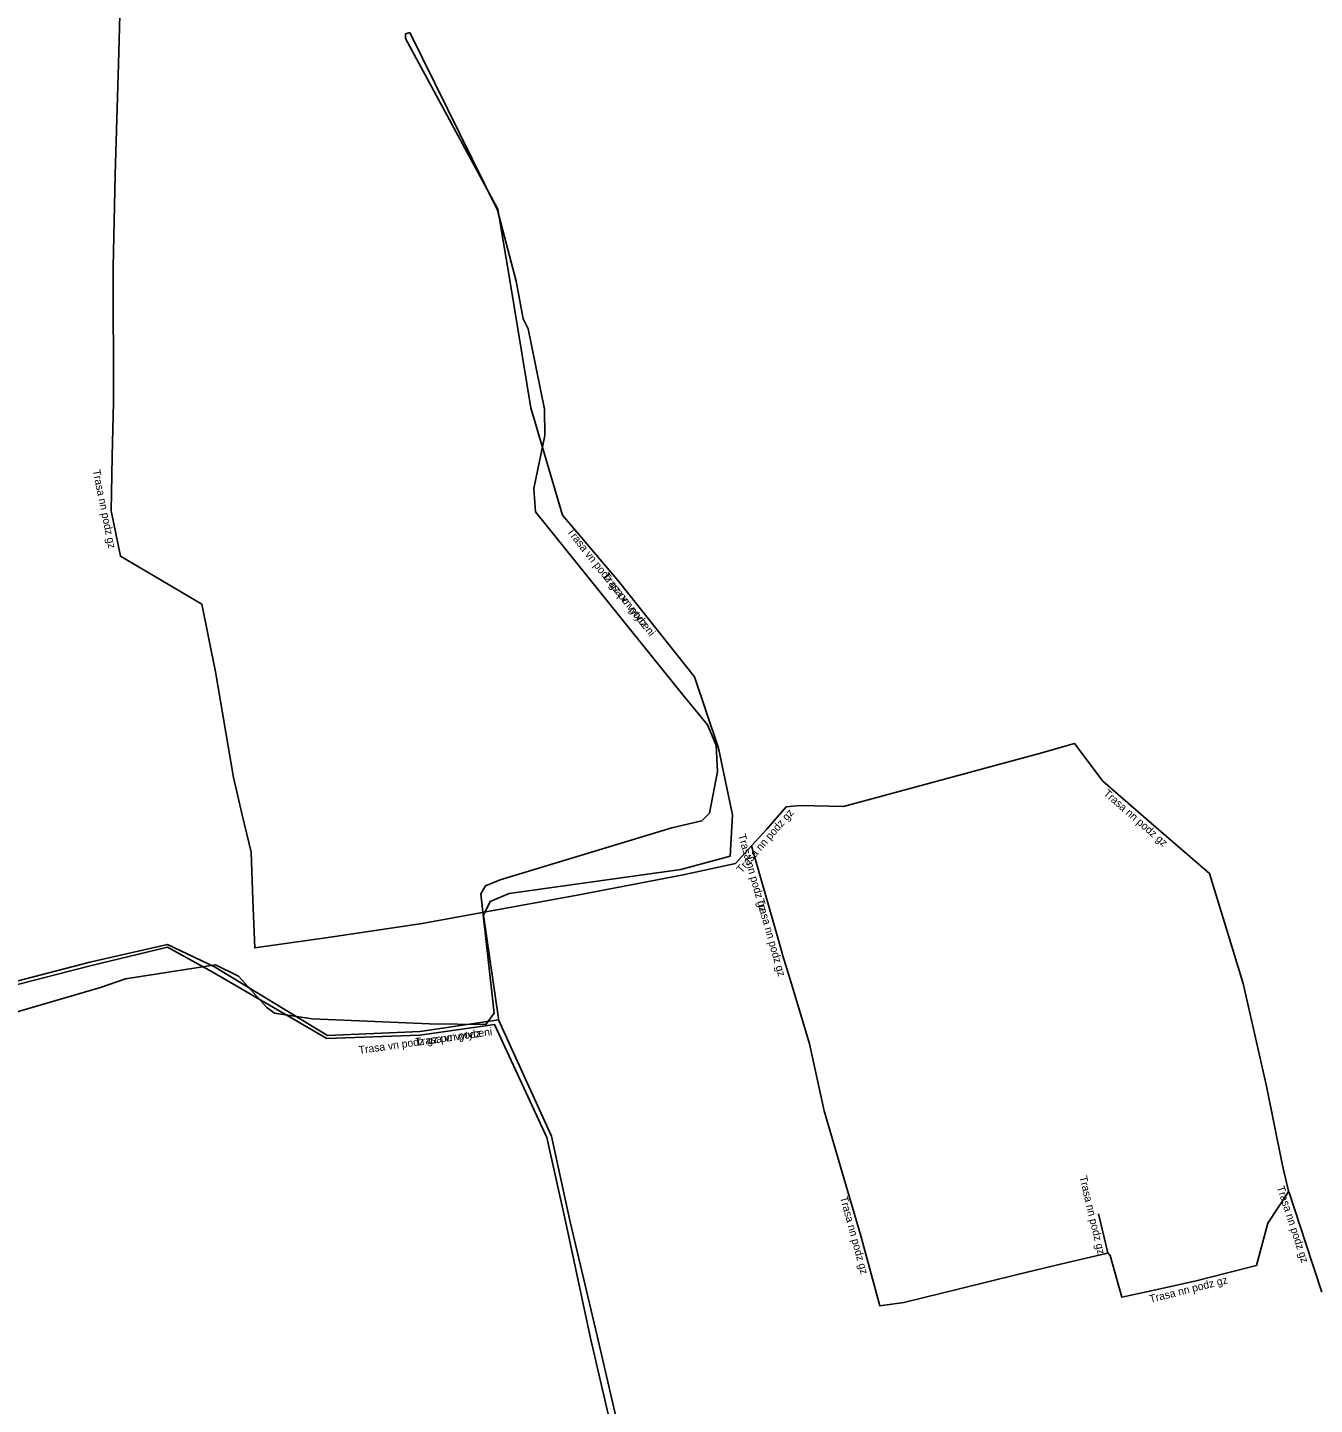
# Model space of a CAD drawing. Extents: x -473162 to -472629, y -1107202 to -1106680.
# Drawn here: x -472952.7 to -472870, y -1106927.1 to -1106838.5 of the extents above; entities that cross this region are included whole.
import ezdxf

# ---------------------------------------------------------------- set-up
doc = ezdxf.new("R2010")
doc.units = 0
for name, color, linetype in [('Popiskový text - Ostatní atributy Trasy', 7, 'Continuous'), ('Spojnice NN', 7, 'Continuous'), ('Spojnice VN', 7, 'Continuous')]:
    doc.layers.add(name, color=color, linetype=linetype)

msp = doc.modelspace()

# ---------------------------------------------------------------- linework, layer by layer
at = {"layer": 'Spojnice NN'}
for points in [[(-472946.635, -1106831.18), (-472946.875, -1106840.1), (-472947.11, -1106847.965), (-472947.235, -1106853.915), (-472947.225, -1106862.605), (-472947.298, -1106866.1), (-472947.37, -1106869.595), (-472947.072, -1106871.052), (-472946.775, -1106872.51), (-472944.158, -1106874.055), (-472941.54, -1106875.6), (-472940.66, -1106879.94), (-472939.5, -1106886.735), (-472938.938, -1106889.132), (-472938.375, -1106891.53), (-472938.258, -1106894.612), (-472938.14, -1106897.695), (-472935.855, -1106897.37), (-472933.57, -1106897.045), (-472927.37, -1106896.135), (-472917.16, -1106894.26), (-472910.59, -1106892.99), (-472907.215, -1106892.26), (-472906.19, -1106891.139)], [(-472903.07, -1106888.54), (-472900.28, -1106888.605), (-472894.015, -1106886.91), (-472887.75, -1106885.215), (-472885.425, -1106884.55), (-472883.6, -1106886.969), (-472880.175, -1106889.945), (-472876.75, -1106892.92), (-472874.586, -1106899.99), (-472873.086, -1106906.584), (-472872.065, -1106911.585), (-472871.66, -1106913.338)], [(-472906.19, -1106891.139), (-472905.205, -1106890.06), (-472903.96, -1106888.629), (-472903.07, -1106888.54)], [(-472906.19, -1106891.139), (-472904.547, -1106896.891)], [(-472903.795, -1106899.457), (-472904.11, -1106898.42), (-472904.547, -1106896.891)], [(-472883.28, -1106917.315), (-472883.385, -1106917.36), (-472886.232, -1106918.028), (-472889.08, -1106918.695), (-472892.735, -1106919.602), (-472896.39, -1106920.51), (-472897.94, -1106920.71), (-472899.16, -1106916.225), (-472900.342, -1106912.198), (-472901.525, -1106908.17), (-472902.455, -1106903.865), (-472903.282, -1106901.142), (-472903.795, -1106899.457)], [(-472871.66, -1106913.338), (-472871.698, -1106913.451), (-472872.985, -1106915.41), (-472873.725, -1106918.135), (-472875.665, -1106918.628), (-472877.605, -1106919.12), (-472879.992, -1106919.638), (-472882.38, -1106920.155), (-472883.125, -1106917.485), (-472883.28, -1106917.315)], [(-472871.66, -1106913.338), (-472871.625, -1106913.433), (-472870.575, -1106916.636), (-472869.525, -1106919.84)], [(-472883.28, -1106917.315), (-472883.88, -1106914.805)]]:
    msp.add_lwpolyline(points, dxfattribs=at)
at = {"layer": 'Spojnice VN'}
for points in [[(-472928.157, -1106838.822), (-472922.521, -1106850.252), (-472921.32, -1106854.81), (-472920.87, -1106857.23), (-472920.56, -1106857.88), (-472919.51, -1106863.05), (-472919.48, -1106864.74), (-472920.2, -1106868.15), (-472920.08, -1106869.65), (-472910.62, -1106881.43), (-472909.03, -1106883.35), (-472908.46, -1106884.65), (-472908.37, -1106886.35), (-472908.9, -1106889.03), (-472909.38, -1106889.53), (-472911.32, -1106889.98), (-472922.36, -1106893.33), (-472923.3, -1106893.7), (-472923.599, -1106894.23), (-472922.74, -1106901.9), (-472923.27, -1106902.63), (-472926.91, -1106902.58), (-472934.44, -1106902.26), (-472936.86, -1106901.89), (-472937.36, -1106901.54), (-472939.18, -1106899.52), (-472940.67, -1106898.78), (-472946.44, -1106899.69), (-472948.05, -1106900.25), (-472988.66, -1106912.1)], [(-472922.467, -1106902.332), (-472922.468, -1106902.242), (-472923.422, -1106895.584), (-472923.002, -1106894.718), (-472921.773, -1106894.208), (-472910.738, -1106892.655), (-472907.572, -1106891.795), (-472907.416, -1106889.148), (-472908.315, -1106884.844), (-472909.857, -1106880.262), (-472914.74, -1106874.108), (-472918.343, -1106869.868), (-472920.385, -1106862.952), (-472921.707, -1106854.874), (-472922.51, -1106850.194), (-472928.434, -1106839.207), (-472928.434, -1106838.907), (-472928.157, -1106838.822)], [(-472922.467, -1106902.332), (-472922.468, -1106902.242), (-472923.422, -1106895.584), (-472923.002, -1106894.718), (-472921.773, -1106894.208), (-472910.738, -1106892.655), (-472907.572, -1106891.795), (-472907.416, -1106889.148), (-472908.315, -1106884.844), (-472909.857, -1106880.262), (-472914.74, -1106874.108), (-472918.343, -1106869.868), (-472920.385, -1106862.952), (-472921.707, -1106854.874), (-472922.51, -1106850.194), (-472928.434, -1106839.207), (-472928.434, -1106838.907), (-472928.157, -1106838.822)], [(-472995.105, -1106913.58), (-472995.09, -1106913.64), (-472991.82, -1106912.59), (-472989.39, -1106911.445), (-472987.65, -1106910.685), (-472975.735, -1106906.39), (-472967.1, -1106902.895), (-472959.132, -1106901.321), (-472948.75, -1106898.612), (-472943.744, -1106897.474), (-472940.736, -1106898.911), (-472933.466, -1106903.33), (-472927.493, -1106903.065), (-472922.467, -1106902.332)], [(-472995.105, -1106913.58), (-472995.09, -1106913.64), (-472991.82, -1106912.59), (-472989.39, -1106911.445), (-472987.65, -1106910.685), (-472975.735, -1106906.39), (-472967.1, -1106902.895), (-472959.132, -1106901.321), (-472948.75, -1106898.612), (-472943.744, -1106897.474), (-472940.736, -1106898.911), (-472933.466, -1106903.33), (-472927.493, -1106903.065), (-472922.467, -1106902.332)], [(-472959.07, -1106901.51), (-472948.712, -1106898.851), (-472943.757, -1106897.659), (-472940.877, -1106899.233), (-472933.493, -1106903.53), (-472927.525, -1106903.315), (-472922.713, -1106902.635), (-472919.352, -1106909.883), (-472918.15, -1106915.27), (-472916.55, -1106922.8), (-472907.68, -1106960.98), (-472902.89, -1106980.6), (-472897.36, -1107003.49), (-472895.13, -1107013.14), (-472893.44, -1107019.01), (-472892.38, -1107024.63)], [(-472959.07, -1106901.51), (-472948.712, -1106898.851), (-472943.757, -1106897.659), (-472940.877, -1106899.233), (-472933.493, -1106903.53), (-472927.525, -1106903.315), (-472922.713, -1106902.635), (-472919.352, -1106909.883), (-472918.15, -1106915.27), (-472916.55, -1106922.8), (-472907.68, -1106960.98), (-472902.89, -1106980.6), (-472897.36, -1107003.49), (-472895.13, -1107013.14), (-472893.44, -1107019.01), (-472892.38, -1107024.63)], [(-472922.467, -1106902.332), (-472919.058, -1106909.81), (-472917.885, -1106915.23), (-472916.11, -1106922.66), (-472907.275, -1106960.875), (-472902.505, -1106980.47), (-472896.935, -1107003.405), (-472894.77, -1107013.03), (-472893.17, -1107018.95), (-472891.83, -1107024.385)], [(-472922.467, -1106902.332), (-472919.058, -1106909.81), (-472917.885, -1106915.23), (-472916.11, -1106922.66), (-472907.275, -1106960.875), (-472902.505, -1106980.47), (-472896.935, -1107003.405), (-472894.77, -1107013.03), (-472893.17, -1107018.95), (-472891.83, -1107024.385)]]:
    msp.add_lwpolyline(points, dxfattribs=at)

# ---------------------------------------------------------------- texts
at = {"layer": 'Popiskový text - Ostatní atributy Trasy'}
for s, rotation, p in [('Trasa nn podz gz', 281.55927, (-472948.568, -1106866.982)), ('Trasa vn podz gz po vytyceni', 308.43086, (-472918.1, -1106870.919)), ('Trasa vn podz', 308.43086, (-472915.809, -1106873.806)), ('Trasa nn podz gz', 319.01246, (-472883.601, -1106887.829)), ('Trasa nn podz gz', 48.98175, (-472906.834, -1106892.923)), ('Trasa nn podz gz', 285.94441, (-472907.063, -1106890.45)), ('Trasa nn podz gz', 285.93921, (-472905.874, -1106894.612)), ('Trasa vn podz gz po vytyceni', 8.0434, (-472931.417, -1106904.522)), ('Trasa vn podz', 8.0434, (-472927.769, -1106904.006)), ('Trasa nn podz gz', 283.44392, (-472885.117, -1106912.424)), ('Trasa nn podz gz', 288.15006, (-472872.421, -1106913.091)), ('Trasa nn podz gz', 285.21728, (-472900.507, -1106913.748)), ('Trasa nn podz gz', 14.23065, (-472880.54, -1106920.535))]:
    msp.add_text(s, height=0.5, rotation=rotation, dxfattribs=at).set_placement(p)

doc.saveas('drawing.dxf')
